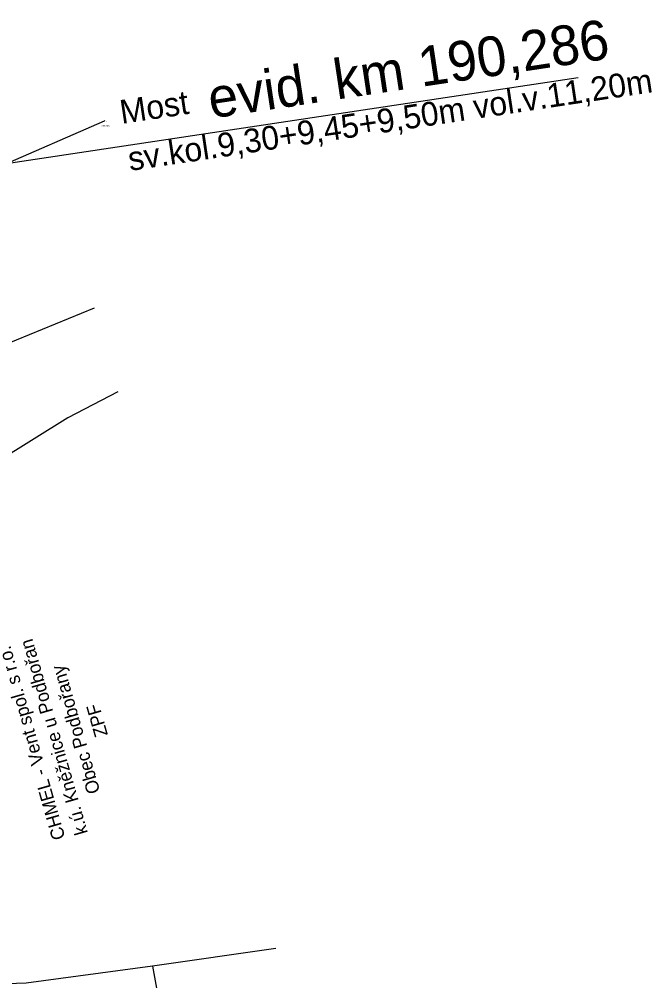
# Model space of a CAD drawing. Extents: x -809973 to -809318, y -1011363 to -1010505.
# Drawn here: x -809781 to -809741.2, y -1010896.6 to -1010836.1 of the extents above; entities that cross this region are included whole.
import ezdxf

# ---------------------------------------------------------------- set-up
doc = ezdxf.new("R2010")
doc.units = 0
for name, color, linetype in [('18b - zaměření - čísla bodů', 7, 'Continuous'), ('18c - zaměření - výšky', 7, 'Continuous'), ('19a - katastr hranice', 7, 'Continuous'), ('19c - katastr popisy', 7, 'Continuous'), ('stav_stav', 7, 'Continuous')]:
    doc.layers.add(name, color=color, linetype=linetype)

# ---------------------------------------------------------------- blocks, each defined once
blk = doc.blocks.new('POINT_DISPLAY')
for p, q in [((-0.021, -0.021), (0.021, 0.021)), ((-0.021, 0.021), (0.021, -0.021))]:
    blk.add_line(p, q)

msp = doc.modelspace()

# ---------------------------------------------------------------- linework, layer by layer
at = {"layer": '19a - katastr hranice'}
for p, q in [((-809764.872, -1010894.603), (-809772.62, -1010895.72)), ((-809772.62, -1010895.72), (-809767.28, -1010925.14))]:
    msp.add_line(p, q, dxfattribs=at)
for points in [[(-809776.307, -1010854.323), (-809788.59, -1010859.35), (-809792.34, -1010860.31)], [(-809774.817, -1010859.571), (-809777.96, -1010861.22), (-809791.19, -1010869.46)], [(-809772.62, -1010895.72), (-809780.58, -1010896.79), (-809783.61, -1010896.9)]]:
    msp.add_lwpolyline(points, dxfattribs=at)
at = {"layer": 'stav_stav'}
for p, q in [((-809745.836, -1010839.815), (-809860.353, -1010857.055)), ((-809788.174, -1010847.963), (-809775.64, -1010842.536))]:
    msp.add_line(p, q, dxfattribs=at)

# ---------------------------------------------------------------- block references
at = {"layer": '18b - zaměření - čísla bodů'}
msp.add_blockref('POINT_DISPLAY', (-809775.64, -1010842.536), dxfattribs=at)

# ---------------------------------------------------------------- texts
msp.add_text('7691', height=0.05, dxfattribs=at).set_placement((-809775.64, -1010842.586))
at = {"layer": '18c - zaměření - výšky'}
msp.add_text('241.783', height=0.1, dxfattribs=at).set_placement((-809775.843, -1010842.899))
at = {"layer": '19c - katastr popisy'}
for s, height, p in [('k.ú. Kněžnice u Podbořan', 0.83338, (-809776.686, -1010887.326)), ('CHMEL - Vent spol. s r.o.', 0.83338, (-809778.107, -1010887.642)), ('Obec Podbořany', 0.83338, (-809775.914, -1010884.74)), ('ZPF', 0.8334, (-809775.429, -1010881.161))]:
    msp.add_text(s, height=height, rotation=105.98192, dxfattribs=at).set_placement(p)
at = {"layer": 'stav_stav'}
for s, height, p in [('evid. km 190,286', 2.5, (-809768.937, -1010842.385)), ('sv.kol.9,30+9,45+9,50m vol.v.11,20m', 1.5, (-809774.049, -1010845.683)), ('Most', 1.5, (-809774.569, -1010842.727))]:
    msp.add_text(s, height=height, rotation=8.5615, dxfattribs=at).set_placement(p)

doc.saveas('drawing.dxf')
